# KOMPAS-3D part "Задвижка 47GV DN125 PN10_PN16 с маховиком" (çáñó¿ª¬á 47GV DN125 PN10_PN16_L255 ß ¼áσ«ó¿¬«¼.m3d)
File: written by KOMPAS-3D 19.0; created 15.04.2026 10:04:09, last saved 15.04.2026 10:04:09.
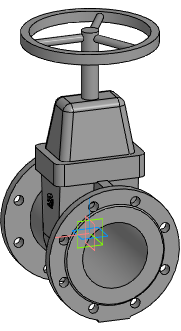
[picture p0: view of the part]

Document properties: Автор: Евгений; Полное имя файла: Z:\3.Личные\kachalov\3d для проектировщиков\2.1 Тип 47GV, 47GV.Z\Задвижка 47GV_DN40-DN600\stp_Задвижка 47GV\Задвижка 47GV DN125 PN10_PN16_L255 с маховиком.m3d

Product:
- Part/product: Задвижка 47GV DN125 PN10_PN16 с маховиком

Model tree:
1. Операция без истории:1  (labels: Задвижка 47GV DN125 PN10_PN16 с маховиком)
